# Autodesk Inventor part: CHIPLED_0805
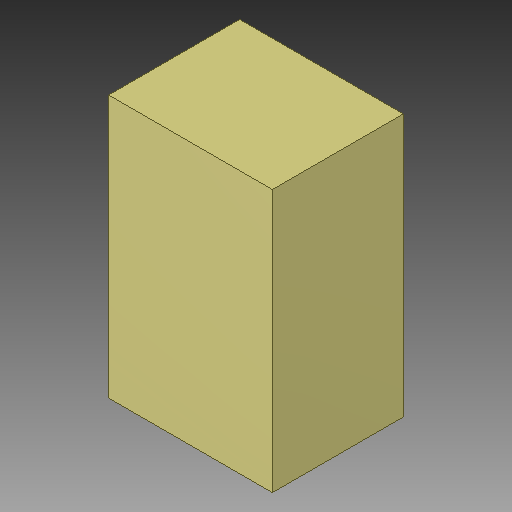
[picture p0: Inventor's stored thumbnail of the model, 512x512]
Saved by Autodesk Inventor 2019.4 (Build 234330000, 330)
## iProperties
Created: 2019-11
Part Number: CHIPLED_0805
Material: Generic
Document SubType Name: Modeling
Designer: Willist
Density: 1 g/cm^3
Appearance: CHIPLED_0805, CHIPLED_0805
Author: Willist
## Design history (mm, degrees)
sketch "CHIPLED_0805, CHIPLED_0805_7"
  geometry: L1 (-0.625, 1.004)-(0.625, 1.004); L2 (0.625, 1.004)-(0.625, -1); L3 (0.625, -1)-(-0.625, -1); L4 (-0.625, -1)-(-0.625, 1.004)
  constraints: 8 end point
extrude "Extrusion1" join sketch "CHIPLED_0805, CHIPLED_0805_7" distance "d0" = 1; taper "d1" = 0 deg
body "Solid1"
